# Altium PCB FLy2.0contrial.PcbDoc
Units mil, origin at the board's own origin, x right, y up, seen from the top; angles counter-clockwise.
Board outline 3894.62 x 3062.25 mil, 2 copper layers (Top Layer, Bottom Layer); 83 components, 65 nets, 258 pads, 55 vias.
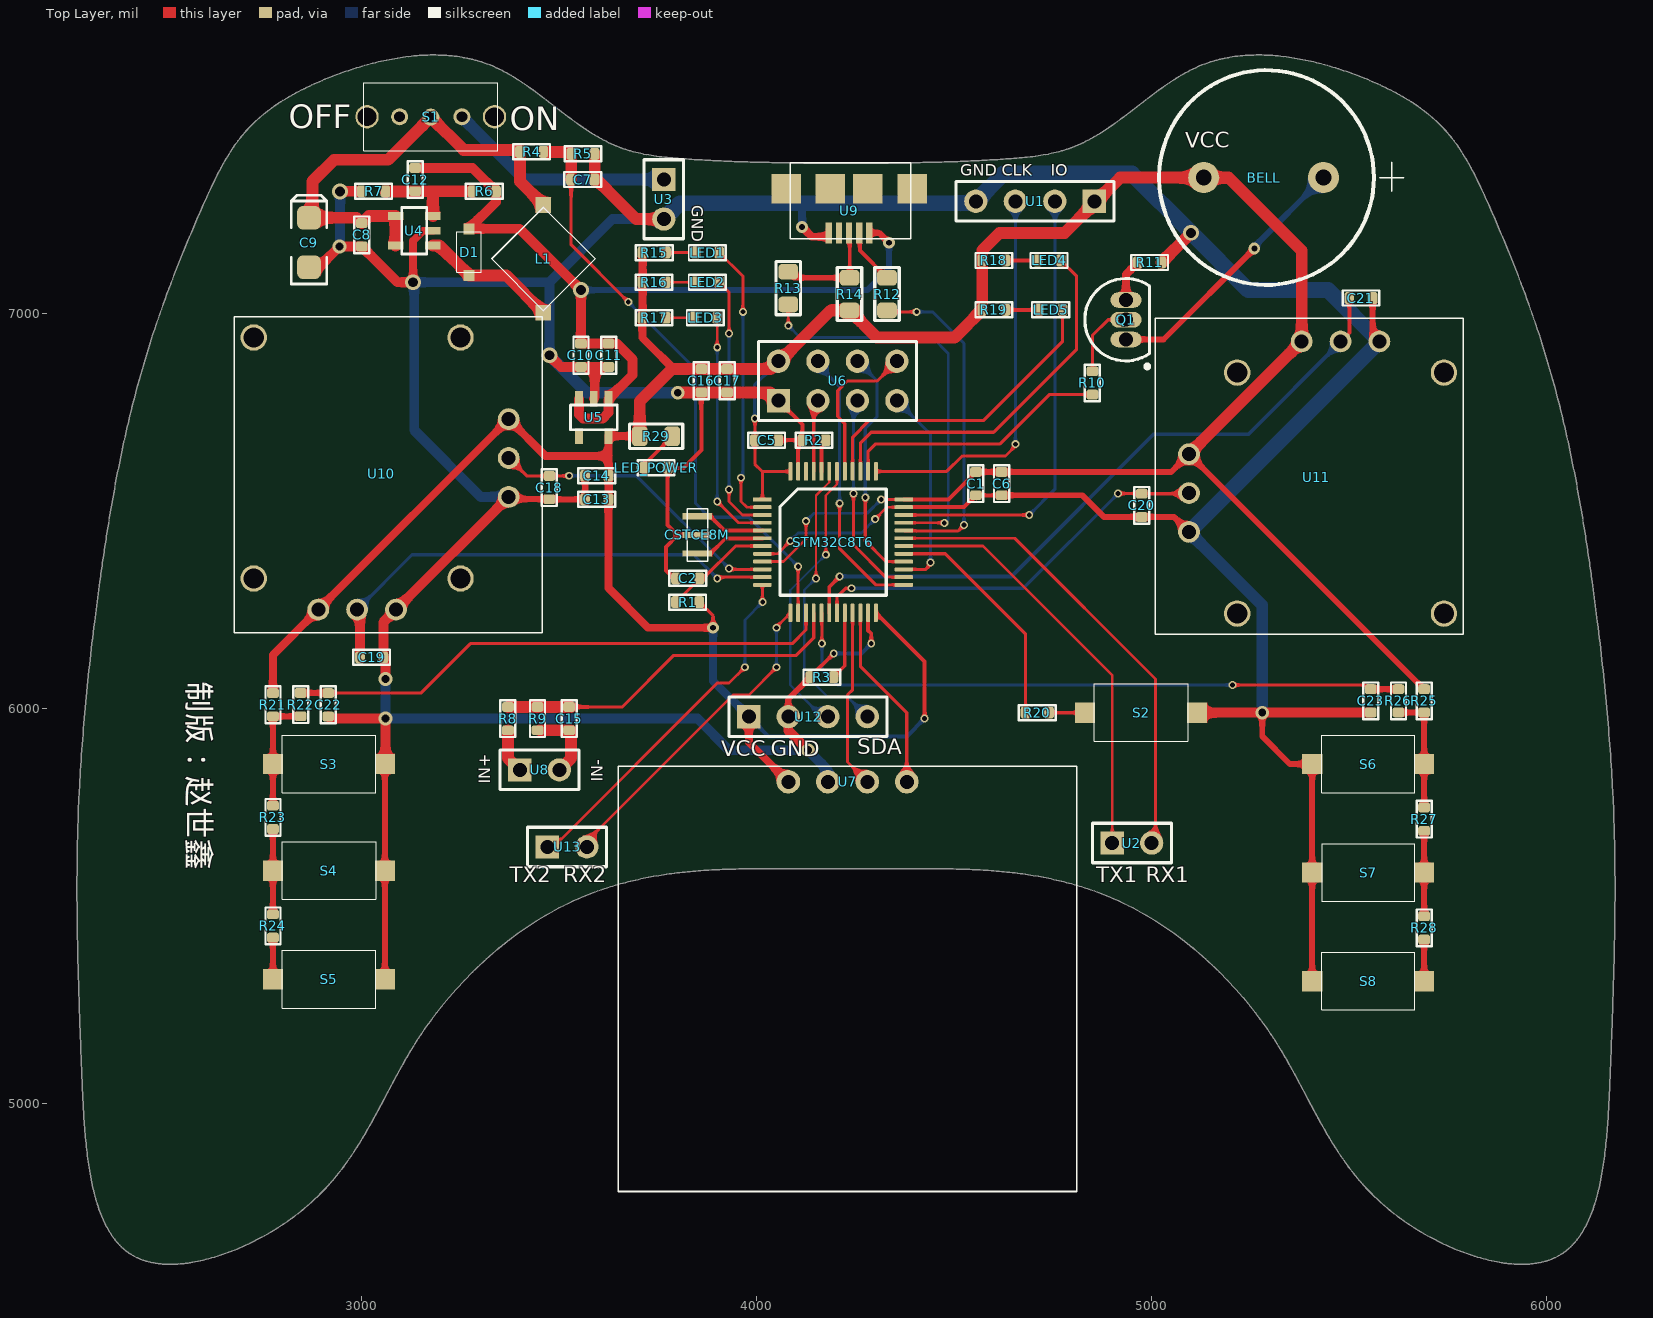
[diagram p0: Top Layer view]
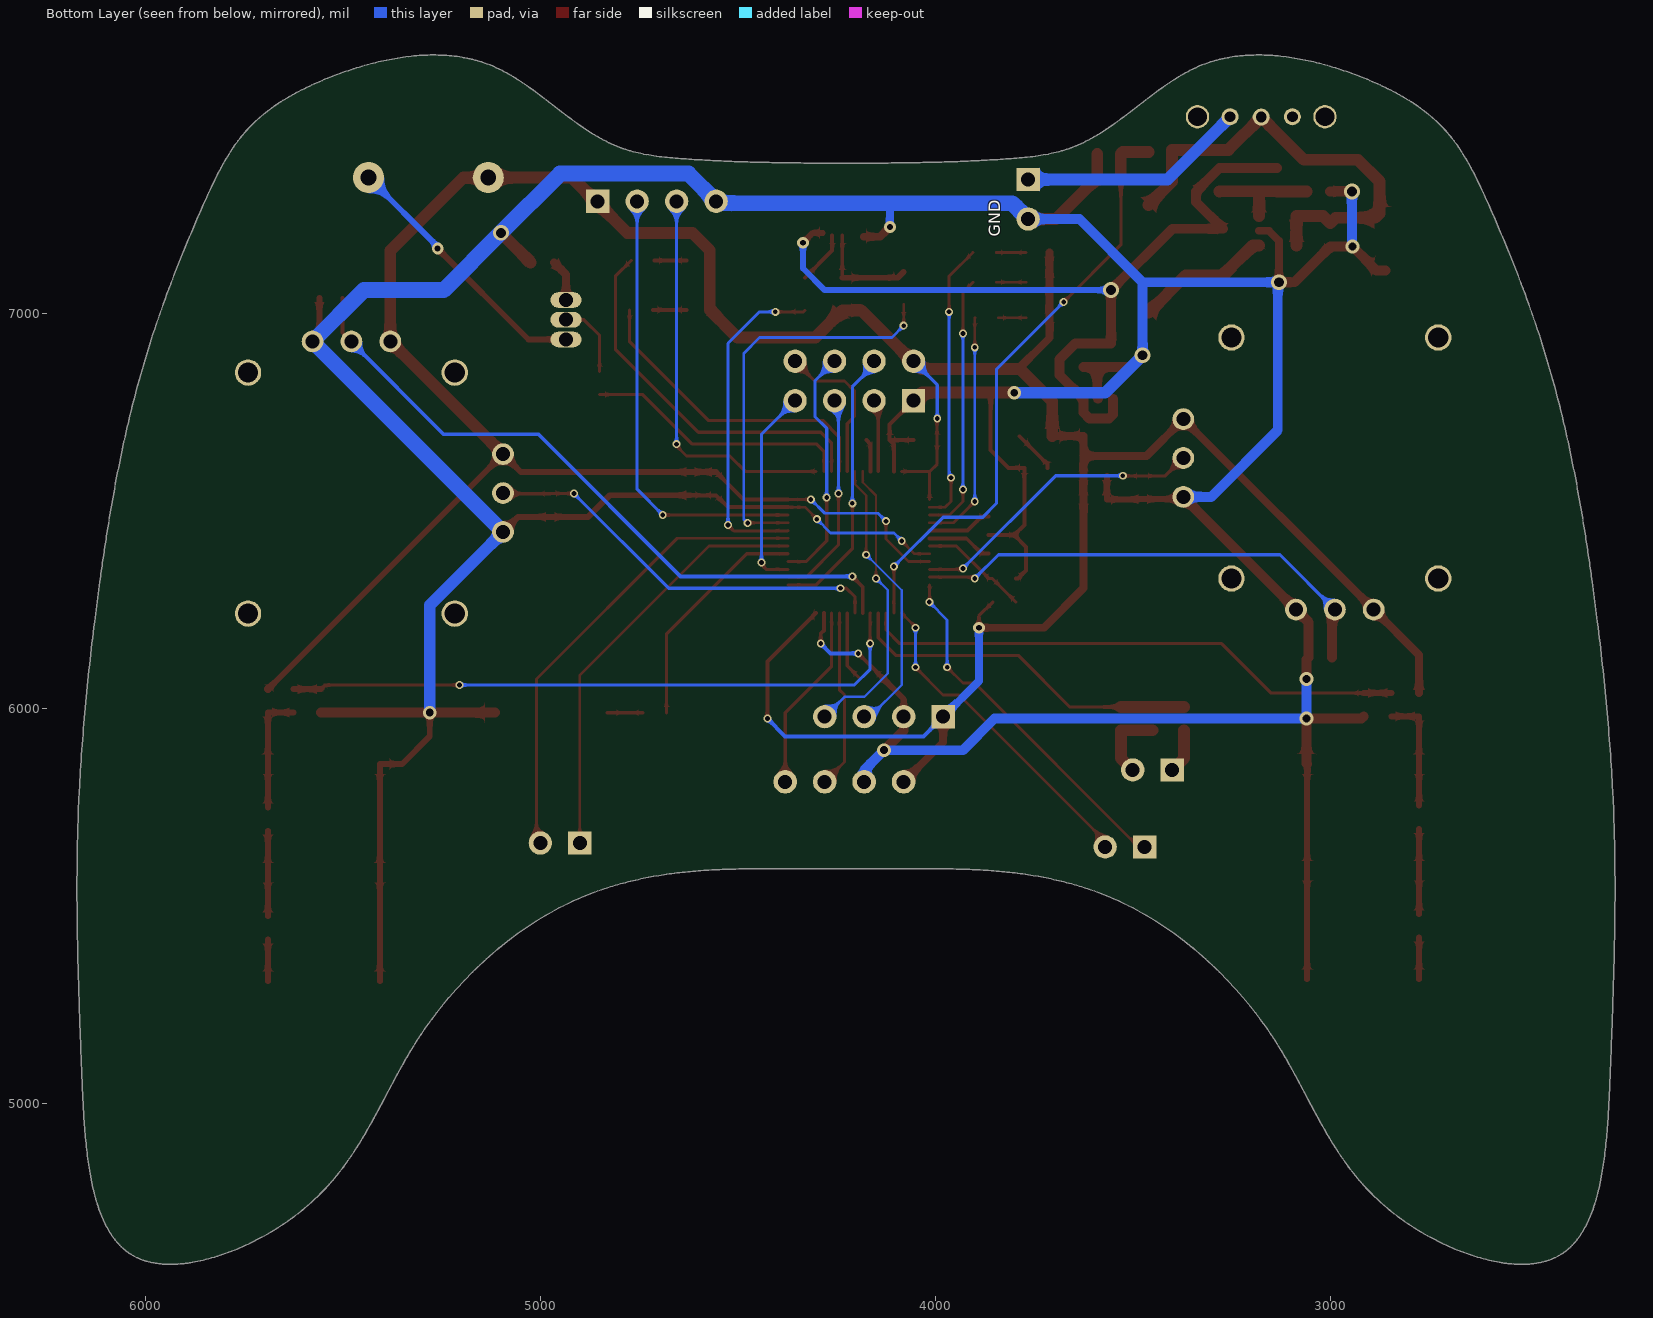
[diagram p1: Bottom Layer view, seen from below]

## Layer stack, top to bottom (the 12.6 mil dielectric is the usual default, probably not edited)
Top Solder: solder mask 0.4, Solder Resist, Dk 3.5
Top Layer: signal copper 1.4
Dielectric 1: dielectric 12.6, FR-4, Dk 4.8
Bottom Layer: signal copper 1.4
Bottom Solder: solder mask 0.4, Solder Resist, Dk 3.5

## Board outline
5365 vertices, not listed, extent 2278.77,4593.18 6173.39,7655.43

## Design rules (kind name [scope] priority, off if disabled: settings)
Clearance [All] p1: gap=6
ComponentClearance [All] p1: gap=0 collisioncheckmode=3 verticalgap=0 showdistances=FALSE
PolygonConnect [All] p1: connectstyle=Relief reliefconductorwidth=10 reliefentries=4 polygonreliefangle="90 Angle" airgapwidth=10
RoutingVias [All] p1: holewidth=12 width=20 viastyle="Through Hole" minholewidth=12 minwidth=20 maxholewidth=35 maxwidth=50
SolderMaskExpansion [All] p1: expansion=4
Width [All] p1: maxlimit=40 minlimit=6 preferedwidth=15
29 further rules are at their usual default settings.

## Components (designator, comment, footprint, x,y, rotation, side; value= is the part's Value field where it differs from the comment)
BELL "BELL" BELL 5131.85,7345 r0 top
C1 "0.1uF" 0603 4555,6570 r270 top
C2 "1uF" 0603 3825.47,6330 r0 top
C5 "0.1uF" 0603 4025,6680 r0 top
C6 "2.2uF" 0603 4620,6570 r270 top
C7 "2.2uF" 0603 3559.53,7340 r180 top
C8 "2.2uF" 0603 3000,7200 r270 top
C9 "10uF" CAP-A 2870,7180 r270 top
C10 "0.1uF" 0603 3555,6895 r270 top
C11 "2.2uF" 0603 3625,6895 r270 top
C12 "0.22uF" 0603 3135,7340 r270 top
C13 "2.2uF" 0603 3595,6530 r180 top
C14 "0.1uF" 0603 3595,6590 r180 top
C15 "2.2uF" 0603 3525,5975 r90 top
C16 "2.2uF" 0603 3860,6830.47 r90 top
C17 "0.1uF" 0603 3925,6830.47 r90 top
C18 "1uF" 0603 3475,6560 r90 top
C19 "1uF" 0603 3025,6130 r180 top
C20 "1uF" 0603 4975,6515 r90 top
C21 "1uF" 0603 5530,7040 r180 top
C22 "1uF" 0603 2915,6010 r90 top
C23 "1uF" 0603 5555,6020 r90 top
CSTCE8M "CSTCE8M" CSTCE8M00G55-R0 3850,6440 r270 top
D1 "MBR0520" SOD_123 3240,7105 r90 top
L1 "Inductor" L_4.7*4.7*1.8 3460,7270 r315 top
LED1 "LED" 0603 3875,7155 r0 top
LED2 "LED" 0603 3875,7080 r0 top
LED3 "LED" 0603 3870,6990 r0 top
LED4 "LED" 0603 4740.47,7135 r0 top
LED5 "LED" 0603 4744.53,7010 r0 top
LED_POWER "LED" 0603 3745,6610 r0 top
Q1 "NPN" TO-226-AA 4935,6985 r0 top
R1 "10K" 0603 3825,6270 r0 top
R2 "10K" 0603 4145,6680 r0 top
R3 "10K" 0603 4165,6080 r0 top
R4 "33K" 0603 3430,7410 r180 top
R5 "33K" 0603 3560,7405 r0 top
R6 "33K" 0603 3310,7310 r180 top
R7 "10K" 0603 3030,7310 r180 top
R8 "33K" 0603 3370,5975 r270 top
R9 "33K" 0603 3445,5975 r270 top
R10 "510" 0603 4850,6825 r90 top
R11 "510" 0603 4995,7130 r180 top
R12 "22R" 0805_1 4330,7050 r90 top
R13 "22R" 0805_1 4080,7065 r90 top
R14 "1.5K" 0805_1 4235,7050 r90 top
R15 "510" 0603 3740.47,7155 r0 top
R16 "510" 0603 3740,7080 r0 top
R17 "510" 0603 3740,6990 r0 top
R18 "510" 0603 4600.47,7135 r0 top
R19 "510" 0603 4600.47,7010 r0 top
R20 "10K" 0603 4710.47,5990 r0 top
R21 "10K" 0603 2775,6010 r90 top
R22 "1K" 0603 2845,6010.47 r90 top
R23 "10K" 0603 2775,5725 r270 top
R24 "10K" 0603 2775,5450 r270 top
R25 "10K" 0603 5690,6020 r270 top
R26 "1K" 0603 5625,6020 r270 top
R27 "10K" 0603 5690,5720.47 r90 top
R28 "10K" 0603 5690,5445 r90 top
R29 "1K" 0805_1 3745,6690 r0 top
S1 "SW-SPST" SWITCH 3175,7500 r180 top
S2 "SW-PB" KEY 4855.16,6062.83 r0 top
S3 "SW-PB" KEY 2798.62,5932.83 r0 top
S4 "SW-PB" KEY 2798.62,5662.83 r0 top
S5 "SW-PB" KEY 2798.62,5387.83 r0 top
S6 "SW-PB" KEY 5666.38,5787.17 r180 top
S7 "SW-PB" KEY 5666.38,5512.17 r180 top
S8 "SW-PB" KEY 5666.38,5237.17 r180 top
STM32C8T6 "STM32C8T6" LQFP_48 4195,6420 r0 top
U1 "Header 4" HDR1X4 4855,7285 r180 top
U2 "Header 2" HDR1X2 4900,5660 r0 top
U3 "Header 2" HDR1X2 3765,7340 r270 top
U4 "LM27313" SOT23-5 3130,7210 r270 top
U5 "MIC5205-3.3" SOT23-5 3588,6735 r0 top
U6 "NRF24L01" HDR2X4 4055,6780 r0 top
U7 "Header 4" OLED 3649.29,5854.37 r0 top
U8 "Header 2" HDR1X2 3400,5845 r0 top
U9 "USB" "Micro USB" 4233.82,7205 r180 top
U10 "YAOGAN-L" yaogan-r 3049.21,6595.51 r270 top
U11 "YAOGAN-R" yaogan-r 5417.4,6585.51 r90 top
U12 "Header 4" HDR1X4 3980,5980 r0 top
U13 "Header 2" HDR1X2 3470,5650 r0 top

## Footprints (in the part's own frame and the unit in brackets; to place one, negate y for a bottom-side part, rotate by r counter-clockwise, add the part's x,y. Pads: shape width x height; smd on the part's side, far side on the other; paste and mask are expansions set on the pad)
0603 [mil]
  rrect50% 25x30 smd: 1(-29.53,0) 2(29.53,0)
  silkscreen extent -47,-19 46,19
0805_1 [mil]
  rrect50% 40x50 smd: 1(-41.34,0) 2(41.34,0)
  silkscreen extent -67,-31 68,31
BELL [mm]
  round 2 hole 1.016: 1(7.7,0) 2(0,0)
  silkscreen extent -2.86,-6.91 12.85,6.91
CAP-A [mil]
  rrect50% 60x60 smd: 1(-63.05,-3.69) 2(61.95,-3.69)
  silkscreen extent -120,-49 104,41
CSTCE8M00G55-R0 [mm]
  rect 0.4x1.9 smd: 1(-1.2,0) 2(0,0) 3(1.2,0)
  silkscreen extent -1.7,-0.65 1.7,0.65
HDR1X2 [mm] "Connector; Header; 2 Position"
  rect 1.5x1.5 hole 0.9: 1(0,0)
  round 1.5 hole 0.9: 2(2.54,0)
  silkscreen extent -1.27,-1.27 3.81,1.27
HDR1X4 [mm] "Connector; Header; 4 Position"
  rect 1.5x1.5 hole 0.9: 1(0,0)
  round 1.5 hole 0.9: 2(2.54,0) 3(5.08,0) 4(7.62,0)
  silkscreen extent -1.27,-1.27 8.89,1.27
HDR2X4 [mm] "Connector; Header; 4x2 Position"
  rect 1.5x1.5 hole 0.9: 1(0,0)
  round 1.5 hole 0.9: 2(0,2.54) 3(2.54,0) 4(2.54,2.54) 5(5.08,0) 6(5.08,2.54) 7(7.62,0) 8(7.62,2.54)
  silkscreen extent -1.27,-1.27 8.89,3.81
KEY [mm]
  rect 1.3x1.3 smd: 1(-0.6,-1.85) 2(6.6,-1.85)
  silkscreen extent 0,-3.7 6,0
L_4.7*4.7*1.8 [mm]
  rect 1x1 smd rot 45: 1(-0.1,0.1) 2(4.8,-4.8)
  silkscreen extent 0,-4.7 4.7,0
LQFP_48 [mm]
  rect 1.2x0.25 smd: 1(-4.587,2.795)
  rrect50% 1.2x0.25 smd: 2(-4.587,2.295) 3(-4.587,1.795) 4(-4.587,1.295) 5(-4.587,0.795) 6(-4.587,0.295) 7(-4.587,-0.205) 8(-4.587,-0.705) 9(-4.587,-1.205) 10(-4.587,-1.705) 11(-4.587,-2.205) 12(-4.587,-2.705) 25(4.513,-2.705) 26(4.513,-2.205) 27(4.513,-1.705) 28(4.513,-1.205) 29(4.513,-0.705) 30(4.513,-0.205) 31(4.513,0.295) 32(4.513,0.795) 33(4.513,1.295) 34(4.513,1.795) 35(4.513,2.295) 36(4.513,2.795)
  rrect50% 0.25x1.2 smd: 13(-2.787,-4.505) 14(-2.287,-4.505) 15(-1.787,-4.505) 16(-1.287,-4.505) 17(-0.787,-4.505) 18(-0.287,-4.505) 19(0.213,-4.505) 20(0.713,-4.505) 21(1.213,-4.505) 22(1.713,-4.505) 23(2.213,-4.505) 24(2.713,-4.505) 37(2.713,4.595) 38(2.213,4.595) 39(1.713,4.595) 40(1.213,4.595) 41(0.713,4.595) 42(0.213,4.595) 43(-0.287,4.595) 44(-0.787,4.595) 45(-1.287,4.595) 46(-1.787,4.595) 47(-2.287,4.595) 48(-2.787,4.595)
  silkscreen extent -3.45,-3.37 3.38,3.46
"Micro USB" [mm]
  rect 0.4x1.35 smd: 1(-1.3,0) 2(-0.65,0) 3(0,0) 4(0.65,0) 5(1.3,0)
  rect 1.9x1.9 smd: 6(-4.05,-2.825) 7(-1.2,-2.825) 8(1.2,-2.825) 9(4.05,-2.825)
  silkscreen extent -3.96,-4.5 3.78,0.38
OLED [mm]
  round 1.524 hole 0.9: 1(10.94,-1) 2(13.48,-1) 3(16.02,-1) 4(18.56,-1)
  silkscreen extent 0,-27.35 29.5,0
SOD_123 [mm]
  rect 0.7x0.7 smd: 1(-0.2,-0.8) 2(2.8,-0.8)
  silkscreen extent 0,-1.6 2.6,0
SOT23-5 [mm]
  rect 0.5x1 smd: 1(0.94,1.27) 2(-0.01,1.27) 3(-0.96,1.27) 4(-0.96,-1.13) 5(0.94,-1.13)
  silkscreen extent -1.51,-0.73 1.49,0.87
SWITCH [mm]
  round 1.5 hole 1.2: 0(-4.091,0.025) 0(4.109,0.025)
  round 1.1 hole 0.7: 1(-1.991,0.025) 2(0.009,0.05) 3(2.009,0.025)
  silkscreen extent -4.29,-2.18 4.31,2.22
TO-226-AA [mm] "TO, Flat Index; 3 In-Line, Axial Leads; Body Dia. 4.8mm; Leads 0.55 x 0.51 mm (max)"
  oval 2x1 hole 0.9: 1(0,-1.27) 2(0,0) 3(0,1.27)
  silkscreen extent -2.65,-3.13 1.52,2.65, body extent -2.65,-2.66 1.52,2.66, height 5.33
yaogan-r [mm]
  round 1.4 hole 0.9: 1(-3.5,8.2) 2(-1,8.2) 3(1.5,8.2) 4(8.75,0.95) 5(8.75,-1.55) 6(8.75,-4.05)
  round 1.7 hole 1.3: 7(-8.75,5.1) 8(6.75,5.1) 9(-8.75,-8.2) 10(6.75,-8.2)
  silkscreen extent -10.08,-9.45 10.24,10.36

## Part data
C1 C2 C5 C6 C7 C8 C15 C16 C17 C18 C19 C20 C21 C22 C23: library part C-0603
C9: library part CAP-T
C10 C11 C12 C13 C14: library part C-0805
D1: library part "Diode 11DQ03", "Schottky Rectifier"
Q1: "NPN Bipolar Transistor"
R1 R2 R3 R12 R13 R14 R15 R16 R17 R18 R19 R20 R21 R22 R23 R24 R25 R26 R27 R28 R29: library part R-0603
R4 R5 R6 R7 R8 R9 R10 R11: library part R0805
S1: "Single-Pole, Single-Throw Switch"
S2 S3 S4 S5 S6 S7 S8: "Switch"
STM32C8T6: library part STM32F103C8T6
U1 U7 U12: "Header, 4-Pin"
U2 U3 U8 U13: "Header, 2-Pin"
U6: library part "Header 4X2", "Header, 4-Pin, Dual row"
U10: library part YAOGAN-R

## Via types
v1: diameter 20, hole 12, Top Layer to Bottom Layer, 40 vias
v2: diameter 35, hole 20, Top Layer to Bottom Layer, 6 vias
v3: diameter 40, hole 25, Top Layer to Bottom Layer, 5 vias
v4: diameter 30, hole 15, Top Layer to Bottom Layer, 4 vias

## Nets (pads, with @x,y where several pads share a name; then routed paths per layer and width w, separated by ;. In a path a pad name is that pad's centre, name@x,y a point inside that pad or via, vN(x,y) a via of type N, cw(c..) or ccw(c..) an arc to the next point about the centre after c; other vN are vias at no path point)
3V3: BELL.2 C1.1 C5.1 C6.1 C13.1 C14.1 C16.2 C17.2 R1.2 R14.1 R15.1 R16.1 R17.1 R18.1 R19.1 R21.2 R25.1 R29.1 STM32C8T6.1 STM32C8T6.9 STM32C8T6.24 STM32C8T6.36 STM32C8T6.48 U1.1 U5.5 U6.2 U7.1 U10.1 U10.6 U11.3 U11.4 U12.1 | length 9052.8
  Top Layer w7: STM32C8T6.9 4067.56,6372.56 4125,6430 v1(4125,6475) ; v1(4315.04,6530.04) STM32C8T6.36
  Top Layer w8: R1.2 3889.53,6235 v4(3889.53,6205) ; v1(3995,6735) 3995.47,6734.53 C5.1 3995.47,6619.53 4014.41,6600.59 STM32C8T6.1 ; 4014.41,6600.91 STM32C8T6.48
  Top Layer w10: U6.2 U6.2@4058.84,6880 ; STM32C8T6.24 4425,6119.45 v1(4425,5975) ; STM32C8T6.36 4485.51,6530.04 C1.1
  Top Layer w15: C1.1 C6.1 5049.53,6599.53 U11.3 R25.1@5689.61,6049.53
  Top Layer w20: R21.2 2775,6136.26 U10.6 U10.1 3465.35,6640 3625,6640 ; C13.1 3624.53,6305.47 3725,6205 v4(3889.53,6205) ; C13.1@3625,6530 3625,6640 ; R29.1 3703.15,6690.51 U5.5 3625,6640 ; R15.1 3710.94,6990.47 R17.1 3710.47,6939.53 3790,6860 ; U12.1 3980,5915 U7.1 ; R25.1@5689.61,6049.53 R25.1
  Top Layer w30: R29.1 3703.66,6778.66 3785,6860 3790,6860 C16.2 C17.2 4035,6860 U6.2 ; U6.2@4058.84,6880 4187.5,7008.66 R14.1 4303.66,6940 4500.94,6940 R19.1 R18.1 4570.94,7160.94 4615,7205 4780,7205 4920,7345 BELL.2 5195,7345 5380,7160 U11.4 U11.3
  Bottom Layer w7: v1(4125,6475) 4145,6495 4280,6495 v1(4315.04,6530.04)
  Bottom Layer w8: v1(3995,6735) 3995,6820 U6.2
  Bottom Layer w10: U12.1 4030,5930 4380,5930 v1(4425,5975)
  Bottom Layer w20: v4(3889.53,6205) 3889.53,6070.47 U12.1
5V: C10.1 C11.1 C12.1 D1.2 R6.1 U5.1 U5.3 U9.1 | length 2195.2
  Top Layer w15: U9.1 4310,7205 v4(4335,7180)
  Top Layer w25: C12.1 3280,7369.53 R6.1 3339.53,7283.27 D1.2 3399.76,7215.24 v3(3555,7060) C10.1 C11.1 3645.47,6924.53 3685,6885 3685,6845 U5.1 3625,6750 3610,6735 3560,6735 3550,6745 3550,6784.8 U5.3
  Bottom Layer w15: v3(3555,7060) 4280,7060 4335,7115 v4(4335,7180)
ADC: C15.2 R8.1 R9.1 STM32C8T6.16 | length 910
  Top Layer w8: C15.2@3530,6004.53 3659.53,6004.53 3790,6135 4100,6135 4144.33,6179.33 STM32C8T6.16
  Top Layer w30: R8.1 R9.1 C15.2@3530,6004.53
ADC_KEY_L: C22.2 R22.2 STM32C8T6.15 | length 1389.2
  Top Layer w8: C22.2 3149.53,6039.53 3275,6165 4090,6165 4124.65,6199.65 STM32C8T6.15
  Top Layer w15: R22.2 2914.53,6040 C22.2
ADC_KEY_R: C23.2 R26.1 STM32C8T6.17 | length 1625.3
  Top Layer w8: STM32C8T6.17 4165,6241.65 v1(4165,6165) ; v1(5205,6060) 5544.53,6060 C23.2
  Top Layer w10: v1@4164.02,6165.98 v1(4165,6165)
  Top Layer w15: C23.2 R26.1
  Bottom Layer w8: v1(4165,6165) 4165,6100 4205,6060 v1(5205,6060)
ADC_L1: C18.2 STM32C8T6.10 U10.2 | length 759.6
  Top Layer w8: U10.2 3417.4,6589.53 C18.2 3524.53,6589.53 v1(3525,6590) ; v1(3930,6355) 3932.13,6352.87 STM32C8T6.10
  Bottom Layer w8: v1(3525,6590) 3695,6590 v1(3930,6355)
ADC_L2: C19.2 STM32C8T6.11 U10.5 | length 1234
  Top Layer w8: v1(3900,6330) 3903.19,6333.19 STM32C8T6.11
  Top Layer w25: U10.5 2995.47,6243.74 C19.2
  Bottom Layer w8: U10.5 3127.17,6390 3840,6390 v1(3900,6330)
ADC_R1: C20.2 STM32C8T6.19 U11.2 | length 1041.2
  Top Layer w8: STM32C8T6.19 4203.39,6283.39 4225,6305 v1(4240,6305) ; v1(4915,6545) 4974.53,6545 C20.2 5092.95,6544.53 U11.2
  Bottom Layer w8: v1(4240,6305) 4675,6305 v1(4915,6545)
ADC_R2: C21.2 STM32C8T6.18 U11.5 | length 1738.2
  Top Layer w10: STM32C8T6.18 4183.7,6308.7 v1(4210,6335) ; U11.5 5500.47,6952.05 C21.2
  Bottom Layer w10: v1(4210,6335) 4645,6335 5005,6695 5245,6695 5478.43,6928.43 U11.5
BAT: S1.1 U3.1 | length 577.5
  Bottom Layer w30: S1.1 3412.42,7340 U3.1
BAT_DAT: C7.2 R4.1 R5.1 STM32C8T6.14 | length 1532.3
  Top Layer w8: C7.2 3530,7175 v1(3675,7030) ; STM32C8T6.14 v1(4105,6360) v1(4105,6360)
  Top Layer w30: R4.1 3525.47,7410 R5.1 3530.47,7340.47 C7.2
  Bottom Layer w8: v1(3675,7030) 3845,6860 3845,6520 3880,6485 3980,6485 v1(4105,6360)
BELL: R10.1 STM32C8T6.38 | length 678.5
  Top Layer w8: STM32C8T6.38 4282.13,6652.13 4300,6670 4615,6670 4740.47,6795.47 R10.1
BOOT0: R2.2 STM32C8T6.44 | length 83.4
  Top Layer w10: STM32C8T6.44 4164.02,6669.49 R2.2
BOOT1: R3.2 STM32C8T6.20 | length 174.5
  Top Layer w8: R3.2 4223.07,6108.54 STM32C8T6.20
CE: STM32C8T6.45 U6.3 | length 183.5
  Top Layer w8: STM32C8T6.45 4144.33,6769.33 U6.3
CSN: STM32C8T6.25 U6.4 | length 698.4
  Top Layer w8: v1(4210,6520) 4210,6405 4301.5,6313.5 STM32C8T6.25
  Bottom Layer w8: U6.4 4155,6870 4210,6815 v1(4210,6520)
GND: C1.2 C2.1 C5.2 C6.2 C7.1 C8.2 C9.2 C10.2 C11.2 C13.2 C14.2 C16.1 C17.1 C18.1 C19.1 C20.1 C21.1 C22.1 C23.1 CSTCE8M.2 LED_POWER.2 R2.1 R3.1 R5.2 R7.2 R11.1 S2.2 S3.2 S4.2 S5.2 S6.2 S7.2 S8.2 STM32C8T6.8 STM32C8T6.23 STM32C8T6.35 STM32C8T6.47 U1.4 U3.2 U4.2 U5.2 U6.1 U7.2 U9.5 U10.3 U10.4 U11.1 U11.6 U12.2 | length 13798.6
  Top Layer w7: STM32C8T6.8 4052.24,6392.24 v1(4085,6425) ; v1(4300,6480) 4330.35,6510.35 STM32C8T6.35
  Top Layer w10: C2.1 3790,6330 3770,6350 3770,6410 3800,6440 ; C16.1 3860,6655 3815,6610 LED_POWER.2 3774.53,6465.47 3800,6440 ; CSTCE8M.2@3865,6440 CSTCE8M.2 3800,6440 ; C5.2 R2.1 ; U6.1 4115.47,6719.53 R2.1 ; STM32C8T6.47 4104.96,6669.49 R2.1 ; R3.1 4195,6139.53 v1(4195,6140) ; STM32C8T6.23 4282.13,6197.87 4290,6190 v1(4290,6165) ; STM32C8T6.35 4524.88,6510.35 C1.2 C6.2 ; v3@5095,7200 v3(5100,7205)
  Top Layer w15: S5.2 S4.2 S3.2 ; U10.3 3377.56,6530.94 3485,6530.94 3485.94,6530 C13.2@3565,6530 ; C13.2@3564.06,6530.94 C13.2@3565,6530 ; C13.2 C13.2@3565,6530 ; C14.2 3565.47,6530.47 C13.2@3565,6530 ; U12.2 4080,6024.53 R3.1 ; C6.2 4824.53,6540.47 4880,6485 4944.06,6485 4945,6485.94 5056.34,6485.94 U11.1 ; v2(5280,5990) 5280,5930 5350,5860 S6.2 S7.2 S8.2 ; C21.1 5559.53,6947.32 U11.6
  Top Layer w20: v3(3130,7080) 3130,7185 3155.4,7210.4 U4.2 ; v4(4115,7220) 4140,7195 U9.5@4180,7195
  Top Layer w25: C9.2@2860,7110 2883.26,7110 v2(2943.73,7170.47) C8.2 3090.47,7080 v3(3130,7080) ; C22.1 2920.47,5975 v2(3060,5975) 3060,5861.54 S3.2 ; v3(2945,7310) R7.2 ; v2(3060,6075) 3060,6124.53 C19.1 3054.53,6218.94 U10.4 U10.3 ; v3(3475,6895) 3504.53,6865.47 C10.2 3590,6865.47 ; U5.2 3590,6787.4 3590,6865.47 ; C11.2 3590,6865.47 ; U12.2 4080,5945 v2(4130,5895) ; S2.2 5115.47,5990.47 5115.94,5990 v2(5280,5990) 5554.53,5990 C23.1
  Top Layer w30: R5.2@3590,7405 3590,7345 3695,7240 U3.2 ; v2(3800,6800) 3800.94,6800.94 C16.1 4034.06,6800.94 U6.1 ; R11.1@5025,7130 v3@5095,7200
  Bottom Layer w7: v1(4085,6425) 4105,6445 4265,6445 v1(4300,6480)
  Bottom Layer w10: v1(4195,6140) 4265,6140 v1(4290,6165)
  Bottom Layer w20: 4110,7280 4115,7275 v4(4115,7220)
  Bottom Layer w25: v2(2943.73,7170.47) 2945,7176.74 v3(2945,7310) ; v2(3060,6075) v2(3060,5975) 3850,5975 3930,5895 v2(4130,5895) 4180,5845 U7.2 ; U10.3 3301.3,6536.46 3132.75,6705 3132.75,7077.25 v3(3130,7080) 3470,7080 ; v3(3475,6895) 3475,7080 3635,7240 U3.2
  Bottom Layer w30: v3(3475,6895) 3570,6800 v2(3800,6800) ; U11.1 5280,6262.28 v2(5280,5990)
  Bottom Layer w40: U3.2 3805,7280 4110,7280 4555,7280 U1.4@4572.5,7297.5 ; U1.4 4625,7355 4950,7355 v3(5100,7205) 5245,7060 5446.85,7060 U11.6 U11.1
IIC1_SCL: STM32C8T6.42 U12.3 | length 718.1
  Top Layer w6: v1(4175,6390) 4175,6540 4203.39,6568.39 STM32C8T6.42
  Bottom Layer w6: v1(4175,6390) 4085,6300 4085,6060 4165,5980 U12.3
IIC1_SDA: STM32C8T6.43 U12.4 | length 767.7
  Top Layer w6: v1(4150,6330) 4150,6540 4183.7,6573.7 STM32C8T6.43
  Top Layer w8: U12.4@4262.44,5997.56 U12.4
  Bottom Layer w6: v1(4150,6330) 4120,6300 4120,6090 4180,6030 4230,6030 U12.4
IIC2_SCL: STM32C8T6.21 U7.3 | length 453.6
  Top Layer w8: STM32C8T6.21 4242.76,6047.76 4230,6035 4230,5865 U7.3
IIC2_SDA: STM32C8T6.22 U7.4 | length 476.3
  Top Layer w8: STM32C8T6.22 4262.44,6107.56 4380,5990 U7.4
IN+: R8.2 U8.1 | length 112.9
  Top Layer w30: R8.2 3370,5875 U8.1
IN-: C15.1 R9.2 U8.2 | length 192.9
  Top Layer w30: R9.2@3450,5945.47 3530,5945.47 3530,5875 U8.2
IRQ: STM32C8T6.41 U6.8 | length 392.6
  Top Layer w8: STM32C8T6.41 4223.07,6721.93 4205,6740 4205,6805 4230,6830 4305,6830 U6.8
KEY: R20.1 STM32C8T6.29 | length 591.5
  Top Layer w8: STM32C8T6.29 4477.76,6392.24 4680.94,6189.06 R20.1
LED1: LED1.2 STM32C8T6.2 | length 717.9
  Top Layer w7: LED1.2 3905,7155 3965,7095 v1(3965,7005) ; v1(3960,6585) 3960,6525 3974.65,6510.35 STM32C8T6.2
  Bottom Layer w7: v1(3960,6585) 3965,6590 v1(3965,7005)
LED2: LED2.2 STM32C8T6.3 | length 664.2
  Top Layer w7: LED2.2 3930,7054.53 v1(3930,6950) ; v1(3930,6555) 3930,6525 3964.33,6490.67 STM32C8T6.3
  Bottom Layer w7: v1(3930,6555) v1(3930,6950)
LED3: LED3.2 STM32C8T6.4 | length 602
  Top Layer w7: LED3.2 3900,6989.53 v1(3900,6915) ; v1(3900,6525) 3954.02,6470.98 STM32C8T6.4
  Bottom Layer w7: v1(3900,6525) v1(3900,6915)
LED4: LED4.2 STM32C8T6.39 | length 959.1
  Top Layer w8: STM32C8T6.39 4262.44,6672.44 4290,6700 4600,6700 4810,6910 4810,7095 LED4.2
LED5: LED5.2 STM32C8T6.40 | length 799
  Top Layer w8: STM32C8T6.40 4242.76,6687.76 4285,6730 4575,6730 4774.06,6929.06 LED5.2
MISO: STM32C8T6.27 U6.7 | length 522.6
  Top Layer w8: STM32C8T6.27 4427.87,6352.87 4440,6365 v1(4440,6370)
  Bottom Layer w8: U6.7 4440,6695 v1(4440,6370)
MOSI: STM32C8T6.28 U6.6 | length 607.5
  Top Layer w8: v1(4275,6535) 4275,6425 4327.44,6372.56 STM32C8T6.28
  Bottom Layer w8: U6.6 4305,6830 4305,6740 4275,6710 v1(4275,6535)
NetBELL_1: BELL.1 Q1.1 | length 672.8
  Top Layer w15: Q1.1 5030,6935 v4(5260,7165)
  Bottom Layer w15: v4(5260,7165) 5260,7170 BELL.1
NetC12_2: C12.2 R6.2 R7.1 U4.3 | length 286.1
  Top Layer w30: R7.1 3134.53,7310 C12.2 3185,7310.47 ; U4.3 3180,7305.47 3185,7310.47 ; R6.2 3280,7310.47 3185,7310.47
NetD1_1: D1.1 L1.2 U4.1 | length 350.5
  Top Layer w30: U4.1 3195.62,7173 D1.1 3365.62,7097.13 L1.2
NetLED1_1: LED1.1 R15.2 | length 75.5
  Top Layer w7: R15.2 LED1.1
NetLED2_1: LED2.1 R16.2 | length 75.9
  Top Layer w7: R16.2 LED2.1
NetLED3_1: LED3.1 R17.2 | length 70.9
  Top Layer w7: R17.2 LED3.1
NetLED4_1: LED4.1 R18.2 | length 80.9
  Top Layer w10: R18.2 LED4.1
NetLED5_1: LED5.1 R19.2 | length 85
  Top Layer w10: R19.2 LED5.1
NetLED_POWER_1: LED_POWER.1 R29.2 | length 109.4
  Top Layer w10: LED_POWER.1 3715.47,6619.13 R29.2
NetQ1_2: Q1.2 R10.2 | length 192
  Top Layer w8: R10.2 4850,6945 4890,6985 Q1.2
NetQ1_3: Q1.3 R11.2 | length 107.6
  Top Layer w20: Q1.3 4935,7099.53 R11.2
NetR12_2: R12.2 U9.2 | length 136
  Top Layer w10: U9.2@4261.14,7198.78 4261.14,7160.2 R12.2
NetR13_2: R13.2 R14.2 U9.3 | length 268.9
  Top Layer w10: R14.2 4235.55,7091.89 U9.3@4235.55,7198.78
  Top Layer w15: R13.2 4095,7091.34 R14.2
NetR20_2: R20.2 S2.1 | length 91.5
  Top Layer w8: R20.2 S2.1
NetR21_1: R21.1 R22.1 R23.1 S3.1 | length 296.1
  Top Layer w15: R23.1 S3.1 R21.1 2844.53,5980.47 R22.1
NetR23_2: R23.2 R24.1 S4.1 | length 215.9
  Top Layer w15: R24.1 S4.1 R23.2
NetR24_2: R24.2 S5.1 | length 105.5
  Top Layer w15: S5.1 R24.2
NetR25_2: R25.2 R26.2 R27.2 S6.1 | length 305.5
  Top Layer w15: R26.2 R25.2 S6.1 R27.2
NetR27_1: R27.1 R28.2 S7.1 | length 216.4
  Top Layer w15: R28.2 S7.1 R27.1
NetR28_1: R28.1 S8.1 | length 105.5
  Top Layer w15: S8.1 R28.1
OSC_IN: CSTCE8M.1 STM32C8T6.5 | length 164.3
  Top Layer w10: CSTCE8M.1@3865,6487.24 3882.76,6487.24 3918.7,6451.3 STM32C8T6.5
OSC_OUT: CSTCE8M.3 STM32C8T6.6 | length 165.5
  Top Layer w10: CSTCE8M.3@3865,6392.76 3882.76,6392.76 3921.61,6431.61 STM32C8T6.6
POWER: C8.1 C9.1 L1.1 R4.2 S1.2 U4.4 U4.5 | length 1170.3
  Top Layer w30: U4.5 U4.4 3018.28,7247.8 C8.1 2986.48,7243.05 2886.31,7243.05 2875,7254.36 2875,7335 2930,7390 3066.61,7390 S1.2 3257.69,7415 R4.2@3400.47,7415 ; R4.2 3400.47,7335.1 L1.1
RESET: C2.2 R1.1 STM32C8T6.7 | length 278
  Top Layer w8: R1.1 3855,6329.53 C2.2 3865,6330 3946.93,6411.93 STM32C8T6.7
RX1: STM32C8T6.31 U2.2 | length 1204.2
  Top Layer w7: STM32C8T6.31 4653.39,6431.61 5010,6075 5010,5670 U2.2
RX2: STM32C8T6.13 U13.2 | length 829.5
  Top Layer w7: U13.2 3570,5665 3940,6035 3980,6035 v1(4050,6105) ; v1(4050,6205) 4050,6207.36 STM32C8T6.13
  Bottom Layer w7: v1(4050,6105) v1(4050,6205)
SCK: STM32C8T6.26 U6.5 | length 530.7
  Top Layer w8: v1(4245,6545) 4245,6415 4326.81,6333.19 STM32C8T6.26
  Bottom Layer w8: v1(4245,6545) 4245,6770 U6.5
SWCLK: STM32C8T6.37 U1.3 | length 1006.8
  Top Layer w8: STM32C8T6.37 4480.91,6600.91 4520,6640 4630,6640 4660,6670 v1(4655,6670)
  Bottom Layer w8: v1(4655,6670) U1.3
SWDIO: STM32C8T6.34 U1.2 | length 1138.6
  Top Layer w8: STM32C8T6.34 v1(4690,6490.67)
  Bottom Layer w8: v1(4690,6490.67) 4755,6555.67 U1.2
TX1: STM32C8T6.30 U2.1 | length 1087.7
  Top Layer w7: STM32C8T6.30 4573.07,6411.93 4900,6085 U2.1
TX2: STM32C8T6.12 U13.1 | length 915.9
  Top Layer w7: U13.1 3485,5650 3900,6065 3930,6065 v1(3970,6105) ; STM32C8T6.12 4014.41,6270.59 v1(4015,6270)
  Bottom Layer w7: v1(3970,6105) 3970,6225 v1(4015,6270)
USB_D+: R13.1 STM32C8T6.33 | length 1024.5
  Top Layer w7: v1(4080,6970) R13.1 ; STM32C8T6.33 4474.02,6470.98 v1(4475,6470)
  Bottom Layer w7: v1(4080,6970) 4110,6940 4445,6940 4485,6900 4485,6480 v1(4475,6470)
USB_D-: R12.1 STM32C8T6.32 | length 848.7
  Top Layer w8: R12.1 4333.66,7005 v1(4405,7005) ; STM32C8T6.32 4373.98,6450 4510,6450 v1(4525,6465)
  Bottom Layer w8: v1(4405,7005) 4445,7005 4525,6925 v1(4525,6465)
pads on no net: S1.0 S1.3 STM32C8T6.46 U5.4 U9.4 U9.6 U9.7 U9.8 U9.9 U10.7 U10.8 U10.9 U10.10 U11.7 U11.8 U11.9 U11.10

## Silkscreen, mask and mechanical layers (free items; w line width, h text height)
Top Overlay:
  text "OFF" at 2815,7470 h60
  text "ON" at 3375,7465 h60
  text "VCC" at 5085,7420 h39.37
  text "GND" at 4515,7350 h30
  text "CLK" at 4620,7350 h30
  text "IO" at 4745,7350 h30
  text "GND" at 3835,7275 h30 r270
  text "制版：赵世鑫" at 2540,6070 h100 r270
  text "SDA" at 4255,5885 h39.37
  text "VCC" at 3910,5880 h39.37
  text "GND" at 4035,5880 h39.37
  text "IN-" at 3610,5815 h30 r90
  text "IN+" at 3325,5810 h30 r90
  text "TX2" at 3375,5560 h40
  text "RX2" at 3510,5560 h40
  text "TX1" at 4860,5560 h40
  text "RX1" at 4985,5560 h40
Bottom Overlay:
  text "GND" at 3835,7195 h30 r270
Mechanical 1:
  drawing of 1595 lines, arcs and shapes, not listed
